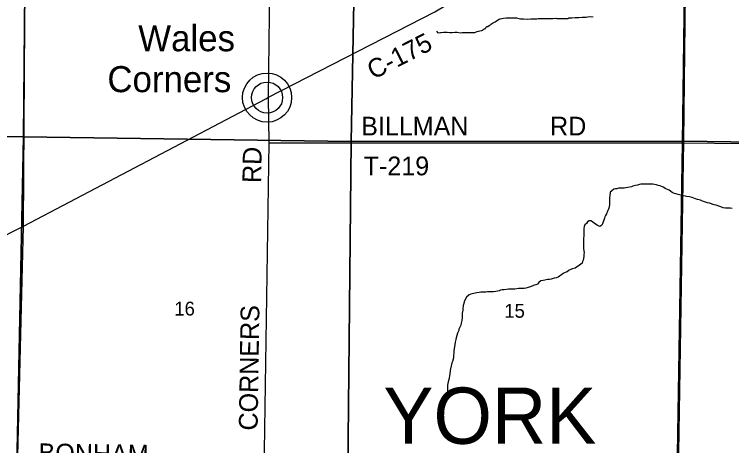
# Model space of a CAD drawing. Extents: x 1588073 to 2013523, y 1090242 to 1357120.
# Drawn here: x 1853753 to 1865230, y 1202525 to 1209425 of the extents above; entities that cross this region are included whole.
import ezdxf

# ---------------------------------------------------------------- set-up
doc = ezdxf.new("R2010")
doc.units = 0
for name, color, linetype in [('GM_X_County_Road', 7, 'Continuous'), ('GM_X_County_Road_Text', 7, 'Continuous'), ('GM_X_Minor_River', 7, 'Continuous'), ('GM_X_Section', 7, 'Continuous'), ('GM_X_Section_Text', 7, 'Continuous'), ('GM_X_Township_Road', 7, 'Continuous'), ('GM_X_Township_Road_Text', 7, 'Continuous'), ('GM_X_Township_Text', 7, 'Continuous'), ('GM_X_Unincorporated', 7, 'Continuous'), ('GM_X_Unincorporated_Location', 7, 'Continuous'), ('GM_X_Unincorporated_Text', 7, 'Continuous')]:
    doc.layers.add(name, color=color, linetype=linetype)

msp = doc.modelspace()

# ---------------------------------------------------------------- linework, layer by layer
at = {"layer": 'GM_X_County_Road'}
for points in [[(1857774, 1208074), (1857774, 1208074), (1857821, 1208099), (1860479, 1209466), (1864502, 1211852), (1866760, 1213313), (1868379, 1214205), (1869843, 1215014), (1871044, 1215663), (1874081, 1217331)], [(1847610, 1202553), (1847610, 1202553), (1848230, 1203001), (1848589, 1203252), (1851848, 1204959), (1853431, 1205800), (1853876, 1206023), (1853901, 1206036), (1857774, 1208074)]]:
    msp.add_lwpolyline(points, dxfattribs=at)
at = {"layer": 'GM_X_Minor_River'}
for points in [[(1860505, 1209154), (1860523, 1209136), (1860541, 1209127), (1860569, 1209135), (1860583, 1209137), (1860617, 1209139), (1860679, 1209138), (1860723, 1209134), (1860759, 1209134), (1860799, 1209139), (1860839, 1209139), (1860887, 1209132), (1860917, 1209134), (1860941, 1209134), (1861052, 1209133), (1861104, 1209135), (1861118, 1209136), (1861132, 1209140), (1861160, 1209150), (1861202, 1209164), (1861232, 1209165), (1861246, 1209171), (1861256, 1209185), (1861276, 1209195), (1861290, 1209199), (1861299, 1209215), (1861313, 1209229), (1861331, 1209233), (1861349, 1209247), (1861371, 1209260), (1861387, 1209272), (1861405, 1209282), (1861446, 1209304), (1861460, 1209314), (1861484, 1209330), (1861510, 1209347), (1861528, 1209353), (1861580, 1209365), (1861624, 1209368), (1861652, 1209370), (1861676, 1209372), (1861732, 1209371), (1861770, 1209371), (1861788, 1209371), (1861822, 1209357), (1861850, 1209354), (1861878, 1209354), (1861900, 1209352), (1861960, 1209349), (1862017, 1209351), (1862031, 1209353), (1862055, 1209355), (1862113, 1209356), (1862133, 1209360), (1862199, 1209361), (1862277, 1209361), (1862297, 1209360), (1862371, 1209360), (1862417, 1209363), (1862435, 1209361), (1862609, 1209360), (1862627, 1209368), (1862670, 1209371), (1862726, 1209373), (1862786, 1209376), (1862836, 1209382), (1862900, 1209381), (1862922, 1209387), (1862964, 1209389), (1863016, 1209386)], [(1865238, 1206318), (1865208, 1206322), (1865176, 1206324), (1865134, 1206324), (1865094, 1206331), (1865058, 1206343), (1865024, 1206357), (1864984, 1206371), (1864949, 1206379), (1864877, 1206403), (1864843, 1206412), (1864809, 1206420), (1864779, 1206430), (1864755, 1206442), (1864733, 1206452), (1864684, 1206464), (1864650, 1206476), (1864626, 1206482), (1864596, 1206494), (1864556, 1206505), (1864508, 1206513), (1864438, 1206527), (1864375, 1206543), (1864339, 1206552), (1864301, 1206566), (1864279, 1206576), (1864251, 1206594), (1864229, 1206610), (1864203, 1206624), (1864175, 1206636), (1864132, 1206660), (1864084, 1206684), (1864052, 1206687), (1864026, 1206695), (1863994, 1206705), (1863970, 1206709), (1863855, 1206709), (1863829, 1206706), (1863803, 1206708), (1863779, 1206706), (1863753, 1206702), (1863725, 1206694), (1863693, 1206686), (1863649, 1206676), (1863625, 1206667), (1863569, 1206657), (1863539, 1206649), (1863509, 1206645), (1863451, 1206645), (1863417, 1206642), (1863393, 1206636), (1863371, 1206632), (1863347, 1206628), (1863309, 1206598), (1863287, 1206578), (1863279, 1206521), (1863277, 1206491), (1863278, 1206417), (1863274, 1206379), (1863270, 1206349), (1863264, 1206325), (1863256, 1206297), (1863246, 1206275), (1863228, 1206236), (1863209, 1206206), (1863199, 1206184), (1863197, 1206162), (1863185, 1206130), (1863173, 1206104), (1863165, 1206076), (1863153, 1206052), (1863119, 1206033), (1863079, 1206053), (1863037, 1206079), (1863005, 1206107), (1862975, 1206119), (1862952, 1206119), (1862926, 1206103), (1862909, 1206078), (1862881, 1206060), (1862869, 1206032), (1862865, 1206000), (1862863, 1205978), (1862863, 1205952), (1862865, 1205930), (1862865, 1205908), (1862863, 1205874), (1862862, 1205842), (1862860, 1205818), (1862858, 1205787), (1862858, 1205735), (1862862, 1205703), (1862862, 1205679), (1862867, 1205643), (1862869, 1205617), (1862867, 1205585), (1862865, 1205557)], [(1862865, 1205557), (1862861, 1205519), (1862853, 1205493), (1862843, 1205471), (1862836, 1205442), (1862772, 1205396), (1862750, 1205382), (1862726, 1205366), (1862680, 1205355), (1862658, 1205345), (1862630, 1205331), (1862596, 1205305), (1862568, 1205293), (1862536, 1205279), (1862508, 1205260), (1862476, 1205236), (1862452, 1205220), (1862426, 1205208), (1862392, 1205202), (1862344, 1205187), (1862314, 1205183), (1862290, 1205181), (1862264, 1205175), (1862242, 1205173), (1862216, 1205167), (1862174, 1205161), (1862142, 1205136), (1862124, 1205108), (1862096, 1205100), (1862072, 1205092), (1862046, 1205084), (1862006, 1205068), (1861976, 1205057), (1861936, 1205045), (1861912, 1205041), (1861884, 1205041), (1861819, 1205037), (1861791, 1205032), (1861761, 1205030), (1861729, 1205028), (1861691, 1205028), (1861659, 1205026), (1861625, 1205024), (1861589, 1205019), (1861557, 1205017), (1861531, 1205015), (1861509, 1205001), (1861457, 1204989), (1861417, 1204985), (1861377, 1204984), (1861349, 1204986), (1861325, 1204984), (1861299, 1204982), (1861240, 1204980), (1861214, 1204978), (1861190, 1204975), (1861150, 1204969), (1861124, 1204963), (1861102, 1204957), (1861076, 1204953), (1861054, 1204949), (1861030, 1204939), (1860988, 1204900), (1860966, 1204864), (1860949, 1204824), (1860943, 1204800), (1860935, 1204766), (1860929, 1204713), (1860929, 1204691), (1860919, 1204643), (1860918, 1204621), (1860918, 1204573), (1860912, 1204529), (1860906, 1204505), (1860902, 1204483), (1860896, 1204451), (1860867, 1204388), (1860863, 1204366), (1860843, 1204322), (1860823, 1204248), (1860819, 1204222), (1860807, 1204183), (1860800, 1204141), (1860790, 1204073), (1860786, 1204045), (1860786, 1204007), (1860780, 1203971), (1860777, 1203929), (1860761, 1203872), (1860755, 1203850), (1860749, 1203824), (1860743, 1203800), (1860733, 1203756), (1860728, 1203726), (1860720, 1203670), (1860716, 1203640), (1860710, 1203611), (1860704, 1203581), (1860694, 1203545), (1860689, 1203521), (1860685, 1203493)], [(1860685, 1203493), (1860681, 1203463), (1860681, 1203327)]]:
    msp.add_lwpolyline(points, dxfattribs=at)
at = {"layer": 'GM_X_Section'}
for points in [[(1848622, 1212783), (1853945, 1212746), (1853897, 1207467), (1848606, 1207490)], [(1853945, 1212746), (1859244, 1212688), (1859142, 1207389), (1853897, 1207467)], [(1859244, 1212688), (1864518, 1212615), (1864459, 1207394), (1859142, 1207389)], [(1864518, 1212615), (1869838, 1212582), (1869772, 1207321), (1864459, 1207394)], [(1848606, 1207490), (1853897, 1207467), (1853792, 1202178), (1848519, 1202205)], [(1853897, 1207467), (1859142, 1207389), (1859088, 1202106), (1853792, 1202178)], [(1864459, 1207394), (1864373, 1202083), (1859088, 1202106), (1859142, 1207389)], [(1864459, 1207394), (1869772, 1207321), (1869714, 1202028), (1864373, 1202083)]]:
    msp.add_lwpolyline(points, close=True, dxfattribs=at)
at = {"layer": 'GM_X_Township_Road'}
for points in [[(1853901, 1206036), (1853958, 1214975), (1854040, 1218203), (1854041, 1218236), (1854041, 1218236)], [(1857821, 1208099), (1857939, 1217728)], [(1864360, 1202052), (1864442, 1207372), (1864502, 1211852)], [(1857750, 1202089), (1857829, 1207371), (1857821, 1208099)], [(1857829, 1207371), (1864442, 1207372)], [(1864442, 1207372), (1866482, 1207350), (1869768, 1207304)], [(1853802, 1202142), (1853901, 1206036)]]:
    msp.add_lwpolyline(points, dxfattribs=at)
at = {"layer": 'GM_X_Unincorporated'}
for radius in [393, 249]:
    msp.add_circle((1857796, 1208093), radius, dxfattribs=at)
at = {"layer": 'GM_X_Unincorporated_Location'}
msp.add_line((1857796, 1208093), (1857796, 1208093), dxfattribs=at)

# ---------------------------------------------------------------- texts
at = {"layer": 'GM_X_County_Road_Text'}
msp.add_text('C-175', height=300, rotation=27.1808, dxfattribs=at).set_placement((1859496, 1208376))
at = {"layer": 'GM_X_Section_Text'}
for s, p in [('16', (1856312, 1204607)), ('15', (1861592, 1204571))]:
    msp.add_text(s, height=221, rotation=0, dxfattribs=at).set_placement(p)
at = {"layer": 'GM_X_Township_Road_Text'}
for s, rotation, p in [('BILLMAN', 0, (1859302, 1207487)), ('RD', 0, (1862325, 1207487)), ('RD', 89.0128, (1857701, 1206725)), ('T-219', 0, (1859342, 1206850)), ('CORNERS', 89.1275, (1857644, 1202765)), ('BONHAM', 359.2259, (1854138, 1202261))]:
    msp.add_text(s, height=300, rotation=rotation, dxfattribs=at).set_placement(p)
at = {"layer": 'GM_X_Township_Text'}
msp.add_text('YORK', height=900, rotation=0, dxfattribs=at).set_placement((1859656, 1202554))
at = {"layer": 'GM_X_Unincorporated_Text'}
for s, p in [('Wales', (1855734, 1208835)), ('Corners', (1855241, 1208180))]:
    msp.add_text(s, height=417, rotation=0, dxfattribs=at).set_placement(p)

doc.saveas('drawing.dxf')
